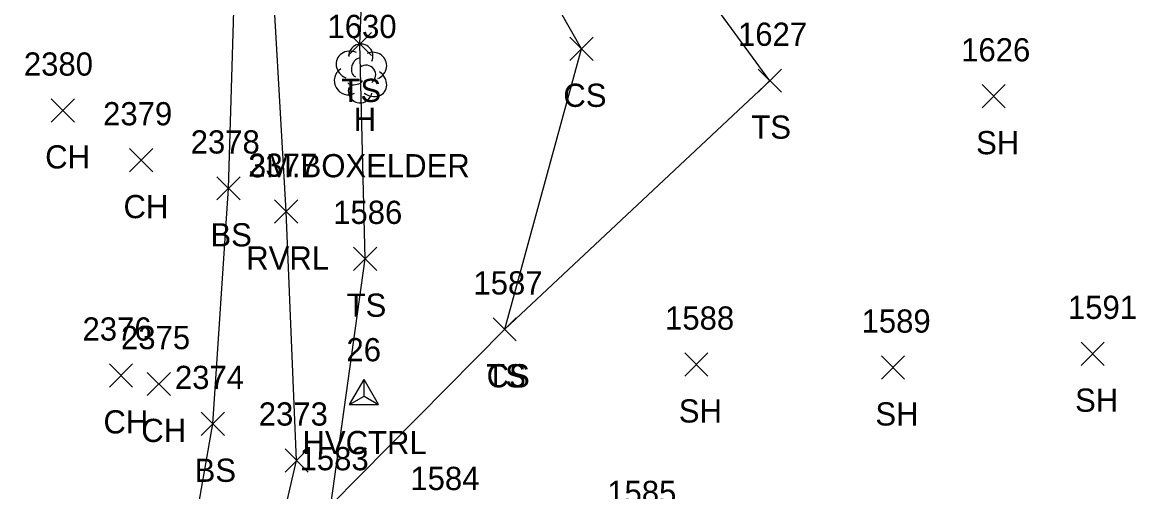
# Model space of a CAD drawing. Extents: x 1459992 to 1461532, y 647785 to 648535.
# Drawn here: x 1461331.1 to 1461426.2, y 648196.8 to 648237.3 of the extents above; entities that cross this region are included whole.
import ezdxf

# ---------------------------------------------------------------- set-up
doc = ezdxf.new("R2010")
doc.units = 0
for name, color, linetype in [('C_A', 7, 'Continuous'), ('C_I', 7, 'Continuous'), ('CPSM', 7, 'Continuous'), ('L_A', 7, 'Continuous'), ('L_C', 7, 'Continuous'), ('L_I', 7, 'Continuous'), ('L_TIC', 7, 'Continuous'), ('LAWE', 7, 'Continuous'), ('LELB', 7, 'Continuous'), ('LTD', 7, 'Continuous')]:
    doc.layers.add(name, color=color, linetype=linetype)

msp = doc.modelspace()

# ---------------------------------------------------------------- linework, layer by layer
at = {"layer": 'CPSM'}
for p, q in [((1461359.265, 648204.36), (1461360.515, 648206.525)), ((1461361.765, 648204.36), (1461360.515, 648206.525)), ((1461360.515, 648205.081), (1461360.515, 648206.525)), ((1461359.265, 648204.36), (1461360.515, 648205.081)), ((1461360.515, 648205.081), (1461360.515, 648205.081)), ((1461360.515, 648205.081), (1461361.765, 648204.36)), ((1461359.265, 648204.36), (1461361.765, 648204.36))]:
    msp.add_line(p, q, dxfattribs=at)
at = {"layer": 'L_TIC'}
for points in [[(1461359.157, 648234.422), (1461361.157, 648236.422)], [(1461361.157, 648234.422), (1461359.157, 648236.422)], [(1461378.226, 648234), (1461380.226, 648236)], [(1461380.226, 648234), (1461378.226, 648236)], [(1461394.441, 648231.259), (1461396.441, 648233.259)], [(1461396.441, 648231.259), (1461394.441, 648233.259)], [(1461413.71, 648229.919), (1461415.71, 648231.919)], [(1461415.71, 648229.919), (1461413.71, 648231.919)], [(1461333.572, 648228.693), (1461335.572, 648230.693)], [(1461335.572, 648228.693), (1461333.572, 648230.693)], [(1461340.315, 648224.41), (1461342.315, 648226.41)], [(1461342.315, 648224.41), (1461340.315, 648226.41)], [(1461347.844, 648221.98), (1461349.844, 648223.98)], [(1461349.844, 648221.98), (1461347.844, 648223.98)], [(1461352.8, 648219.98), (1461354.8, 648221.98)], [(1461354.8, 648219.98), (1461352.8, 648221.98)], [(1461359.601, 648215.915), (1461361.601, 648217.915)], [(1461361.601, 648215.915), (1461359.601, 648217.915)], [(1461371.62, 648209.835), (1461373.62, 648211.835)], [(1461373.62, 648209.835), (1461371.62, 648211.835)], [(1461371.62, 648209.835), (1461373.62, 648211.835)], [(1461373.62, 648209.835), (1461371.62, 648211.835)], [(1461422.231, 648207.731), (1461424.231, 648209.731)], [(1461424.231, 648207.731), (1461422.231, 648209.731)], [(1461388.116, 648206.805), (1461390.116, 648208.805)], [(1461390.116, 648206.805), (1461388.116, 648208.805)], [(1461405.042, 648206.546), (1461407.042, 648208.546)], [(1461407.042, 648206.546), (1461405.042, 648208.546)], [(1461338.59, 648205.864), (1461340.59, 648207.864)], [(1461340.59, 648205.864), (1461338.59, 648207.864)], [(1461341.848, 648205.125), (1461343.848, 648207.125)], [(1461343.848, 648205.125), (1461341.848, 648207.125)], [(1461346.487, 648201.693), (1461348.487, 648203.693)], [(1461348.487, 648201.693), (1461346.487, 648203.693)], [(1461353.706, 648198.541), (1461355.706, 648200.541)], [(1461355.706, 648198.541), (1461353.706, 648200.541)]]:
    msp.add_lwpolyline(points, dxfattribs=at)
at = {"layer": 'LAWE'}
msp.add_lwpolyline([(1461220.159, 648021.615), (1461235.47, 648039.294), (1461252.966, 648048.327), (1461267.663, 648064.216), (1461276.22, 648071.524), (1461288.833, 648087.698), (1461307.75, 648107.551), (1461316.994, 648127.784), (1461326.453, 648138.792), (1461334.868, 648155.88), (1461340.573, 648163.303), (1461349.799, 648178.335), (1461354.706, 648199.541), (1461353.8, 648220.98), (1461352.341, 648246.452), (1461354.078, 648262.219), (1461358.254, 648276.136), (1461371.394, 648295.376), (1461381.983, 648319.016), (1461394.178, 648330.617), (1461418.251, 648335.818), (1461440.86, 648338.789), (1461464.612, 648337.5), (1461486.388, 648342.471)], dxfattribs=at)
at = {"layer": 'LELB'}
for points in [[(1461216.735, 648025.379), (1461232.531, 648043.682), (1461249.111, 648052.696), (1461265.41, 648068.573), (1461273.176, 648074.771), (1461285.769, 648090.042), (1461304.003, 648110.191), (1461314.102, 648129.874), (1461321.787, 648141.876), (1461329.36, 648157.887), (1461338.075, 648167.022), (1461343.94, 648182.363), (1461347.487, 648202.693), (1461348.844, 648222.98), (1461349.522, 648245.94), (1461349.946, 648262.877), (1461353.497, 648277.365), (1461366.77, 648299.226), (1461380.277, 648319.065), (1461391.623, 648332.953), (1461418.599, 648338.961), (1461441.306, 648340.652), (1461465.695, 648340.733), (1461485.923, 648346.235)], [(1461358.31, 648179.355), (1461357.653, 648195.692), (1461360.601, 648216.915), (1461360.157, 648235.422), (1461360.989, 648255.356), (1461365.028, 648278.404), (1461376.071, 648295.04), (1461384.29, 648312.493), (1461396.995, 648324.631), (1461420.097, 648331.579), (1461440.679, 648334.945), (1461465.222, 648335.03), (1461486.95, 648334.589)], [(1461357.653, 648195.692), (1461372.62, 648210.835), (1461379.226, 648235), (1461368.439, 648254.002), (1461374.317, 648275.061), (1461388.077, 648297.078), (1461390.715, 648303.649), (1461401.544, 648316.282), (1461420.081, 648328.389), (1461441.846, 648332.112), (1461465.283, 648329.963)], [(1461372.62, 648210.835), (1461395.441, 648232.259), (1461377.271, 648257.091), (1461379.775, 648272.055), (1461393.455, 648294.262), (1461394.351, 648300.848), (1461403.621, 648312.479), (1461422.059, 648324.886), (1461442.394, 648328.132), (1461465.283, 648329.963), (1461486.61, 648325.746)]]:
    msp.add_lwpolyline(points, dxfattribs=at)
at = {"layer": 'LTD'}
msp.add_line((1461360.187, 648232.933), (1461360.187, 648232.933), dxfattribs=at)
msp.add_line((1461360.187, 648232.933), (1461360.187, 648232.933), dxfattribs=at)
msp.add_arc((1461360.234, 648234.367), 1.047, 335.52715, 180.95627, dxfattribs=at)
for centre, major_axis, ratio, start_param, end_param in [((1461359.396, 648233.6), (1.21, -0.512), 0.895232, 1.570796, 4.712389), ((1461361.229, 648233.517), (-1.141, -0.483), 0.949671, 1.570796, 4.712389), ((1461359.979, 648233.392), (-0.208, -0.792), 0.645439, 3.141593, 6.283185), ((1461360.687, 648232.767), (-0.5, 0.667), 0.989748, 3.141593, 6.283185), ((1461359.104, 648232.225), (0.584, -1.042), 0.959034, 3.141593, 6.283185), ((1461361.187, 648232.1), (-1.09, 0.792), 0.841452, 1.570796, 4.712389), ((1461359.729, 648232.183), (-0.625, -0.083), 0.423636, 0, 3.141593), ((1461360.188, 648231.433), (0.265, 1.061), 0.942809, 1.570796, 4.712389)]:
    msp.add_ellipse(centre, major_axis=major_axis, ratio=ratio, start_param=start_param, end_param=end_param, dxfattribs=at)

# ---------------------------------------------------------------- texts
at = {"layer": 'C_A'}
msp.add_text('HVCTRL', height=2, dxfattribs=at).set_placement((1461355.208, 648200.081))
at = {"layer": 'C_I'}
msp.add_text('26', height=2, dxfattribs=at).set_placement((1461358.995, 648208.081))
at = {"layer": 'L_A'}
for s, p in [('TS', (1461358.566, 648230.422)), ('CS', (1461377.667, 648230)), ('H', (1461359.62, 648227.933)), ('TS', (1461393.851, 648227.259)), ('SH', (1461413.198, 648225.919)), ('CH', (1461333.06, 648224.693)), ('CH', (1461339.803, 648220.41)), ('BS', (1461347.285, 648217.98)), ('RVRL', (1461350.367, 648215.98)), ('TS', (1461359.011, 648211.915)), ('TS', (1461371.029, 648205.835)), ('CS', (1461371.061, 648205.835)), ('SH', (1461421.719, 648203.731)), ('SH', (1461387.604, 648202.805)), ('SH', (1461404.53, 648202.546)), ('CH', (1461338.078, 648201.864)), ('CH', (1461341.336, 648201.125)), ('BS', (1461345.928, 648197.693))]:
    msp.add_text(s, height=2, dxfattribs=at).set_placement(p)
at = {"layer": 'L_C'}
msp.add_text('3M.BOXELDER', height=2, dxfattribs=at).set_placement((1461350.589, 648223.933))
at = {"layer": 'L_I'}
for s, p in [('1630', (1461357.361, 648235.933)), ('1627', (1461392.701, 648235.259)), ('1626', (1461411.915, 648233.919)), ('2380', (1461331.226, 648232.693)), ('2379', (1461338.047, 648228.41)), ('2378', (1461345.585, 648225.98)), ('2377', (1461350.54, 648223.98)), ('1586', (1461357.853, 648219.915)), ('1587', (1461369.927, 648213.835)), ('1587', (1461369.927, 648213.835)), ('1591', (1461421.105, 648211.731)), ('1588', (1461386.423, 648210.805)), ('2376', (1461336.275, 648209.864)), ('1589', (1461403.341, 648210.546)), ('2375', (1461339.588, 648209.125)), ('2374', (1461344.228, 648205.693)), ('2373', (1461351.446, 648202.541)), ('1583', (1461354.96, 648198.692)), ('1583', (1461354.96, 648198.692)), ('1584', (1461364.497, 648196.989)), ('1585', (1461381.446, 648195.782))]:
    msp.add_text(s, height=2, dxfattribs=at).set_placement(p)

doc.saveas('drawing.dxf')
